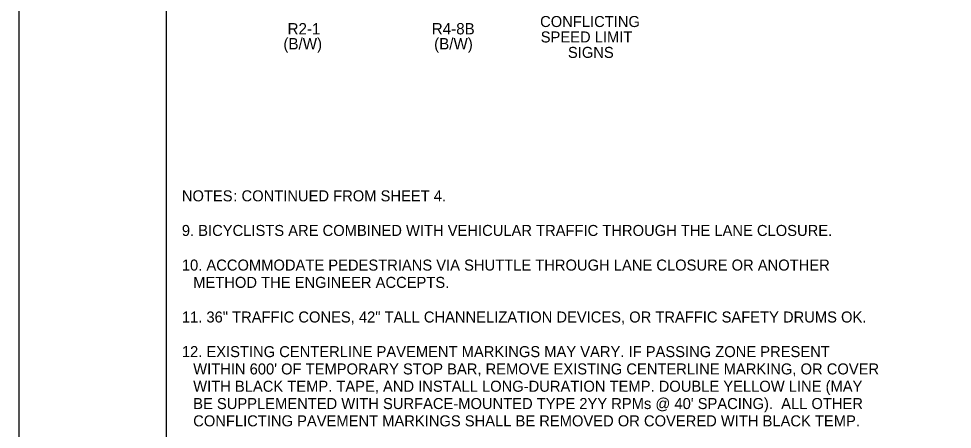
# Model space of a CAD drawing. Extents: x 99982 to 100176, y 99905 to 100011.
# Drawn here: x 100059.06 to 100065, y 99912.89 to 99915.5 of the extents above; entities that cross this region are included whole.
import ezdxf

# ---------------------------------------------------------------- set-up
doc = ezdxf.new("R2010")
doc.units = 0
for name, color, linetype in [('SH_GI_GeneralNotesBodyText', 7, 'Continuous'), ('SH_GI_PlotLimits', 7, 'Continuous'), ('SH_GI_SheetBorder', 7, 'Continuous'), ('TR_SN_ConstructionSigns', 7, 'Continuous'), ('TR_WZ_WorkZoneDetails', 7, 'Continuous')]:
    doc.layers.add(name, color=color, linetype=linetype)

msp = doc.modelspace()

# ---------------------------------------------------------------- linework, layer by layer
at = {"layer": 'SH_GI_PlotLimits'}
msp.add_lwpolyline([(100059.0625, 99909.6875), (100076.0625, 99909.6875), (100076.0625, 99920.6875), (100059.0625, 99920.6875)], close=True, dxfattribs=at)
at = {"layer": 'SH_GI_SheetBorder'}
msp.add_line((100060, 99920.375), (100060, 99910), dxfattribs=at)

# ---------------------------------------------------------------- texts
at = {"layer": 'SH_GI_GeneralNotesBodyText'}
for s, p in [('NOTES', (100060.1, 99914.3384)), (': CONTINUED FROM SHEET 4.', (100060.4275, 99914.3384)), ('9. BICYCLISTS ARE COMBINED WITH VEHICULAR TRAFFIC THROUGH THE LANE CLOSURE.', (100060.1, 99914.1186)), ('10. ACCOMMODATE PEDESTRIANS VIA SHUTTLE THROUGH LANE CLOSURE OR ANOTHER ', (100060.1, 99913.8988)), ('METHOD THE ENGINEER ACCEPTS.', (100060.1722, 99913.7889)), ('11. 36" TRAFFIC CONES, 42" TALL CHANNELIZATION DEVICES, OR TRAFFIC SAFETY DRUMS OK.', (100060.1, 99913.5691)), ('12. EXISTING CENTERLINE PAVEMENT MARKINGS MAY VARY. IF PASSING ZONE PRESENT ', (100060.1, 99913.3493)), ("WITHIN 600' OF TEMPORARY STOP BAR, REMOVE EXISTING CENTERLINE MARKING, OR COVER ", (100060.1722, 99913.2394)), ('WITH BLACK TEMP. TAPE, AND INSTALL LONG-DURATION TEMP. DOUBLE YELLOW LINE (MAY ', (100060.1722, 99913.1295)), ("BE SUPPLEMENTED WITH SURFACE-MOUNTED TYPE 2YY RPMs @ 40' SPACING).  ALL OTHER ", (100060.1722, 99913.0196)), ('CONFLICTING PAVEMENT MARKINGS SHALL BE REMOVED OR COVERED WITH BLACK TEMP. ', (100060.1722, 99912.9097))]:
    msp.add_text(s, height=0.07, rotation=360, dxfattribs=at).set_placement(p)
at = {"layer": 'TR_SN_ConstructionSigns'}
for s, p in [('R2-1', (100060.772, 99915.3983)), ('(B/W)', (100060.7456, 99915.3032))]:
    msp.add_text(s, height=0.072, rotation=360, dxfattribs=at).set_placement(p)
for s, p in [('CONFLICTING', (100062.3778, 99915.4452)), ('SPEED LIMIT', (100062.3816, 99915.3472)), ('SIGNS', (100062.5546, 99915.2492))]:
    msp.add_text(s, height=0.07, dxfattribs=at).set_placement(p)
at = {"layer": 'TR_WZ_WorkZoneDetails'}
for s, p in [('R4-8B', (100061.689, 99915.3983)), ('(B/W)', (100061.704, 99915.3032))]:
    msp.add_text(s, height=0.072, rotation=360, dxfattribs=at).set_placement(p)

doc.saveas('drawing.dxf')
